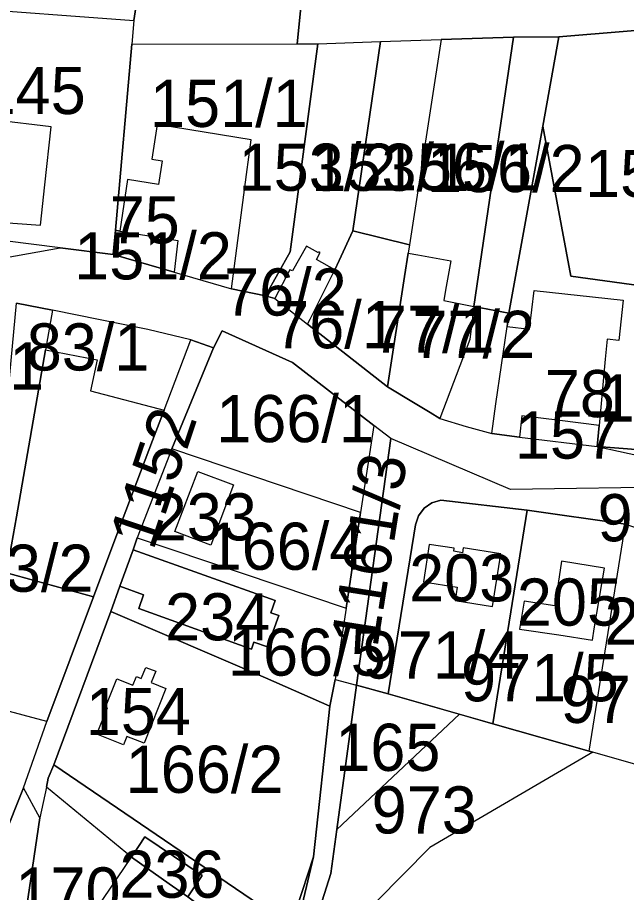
# Model space of a CAD drawing. Extents: x -623250 to -619626, y -1079612 to -1075424.
# Drawn here: x -621418.9 to -621289.7, y -1077664.2 to -1077478.6 of the extents above; entities that cross this region are included whole.
import ezdxf

# ---------------------------------------------------------------- set-up
doc = ezdxf.new("R2010")
doc.units = 0
for name, color, linetype in [('Hranice převzatá (k_ú_Džbánov - vnitřní obvod)', 7, 'Continuous'), ('Hranice šetřená (k_ú_Džbánov - vnitřní obvod)', 7, 'Continuous'), ('Parcela nároku', 7, 'Continuous'), ('Parcelní číslo', 7, 'Continuous')]:
    doc.layers.add(name, color=color, linetype=linetype)

msp = doc.modelspace()

# ---------------------------------------------------------------- linework, layer by layer
at = {"layer": 'Hranice převzatá (k_ú_Džbánov - vnitřní obvod)'}
msp.add_lwpolyline([(-621214.74, -1077657.83), (-621238.69, -1077651.01), (-621258.47, -1077645.38), (-621278, -1077639.82), (-621297.64, -1077634.23), (-621318.07, -1077628.41), (-621340.28, -1077622.09)], dxfattribs=at)
at = {"layer": 'Hranice šetřená (k_ú_Džbánov - vnitřní obvod)'}
msp.add_lwpolyline([(-621340.28, -1077622.09), (-621346.96, -1077620.27), (-621351.15, -1077650.83), (-621352.43, -1077660.2), (-621359.74, -1077683.39), (-621370.61, -1077717.85), (-621377.7, -1077716.06), (-621379.95, -1077714.81)], dxfattribs=at)
at = {"layer": 'Parcela nároku'}
for points in [[(-621431.19, -1077464.42), (-621432.42, -1077476.42), (-621394.2, -1077479.27), (-621389.22, -1077446.41), (-621387.12, -1077432.52), (-621431.55, -1077429.78), (-621432.54, -1077450.72)], [(-621355.58, -1077444.76), (-621359.53, -1077484.2), (-621355.15, -1077484.19), (-621341.9, -1077483.74), (-621329.01, -1077483.3), (-621313.65, -1077482.77), (-621304.05, -1077482.73), (-621260.58, -1077479.13), (-621259.56, -1077479.1), (-621135.81, -1077472.04), (-621135.22, -1077433.98), (-621245.55, -1077439.34)], [(-621355.58, -1077444.76), (-621389.22, -1077446.41), (-621394.2, -1077479.27), (-621394.64, -1077484.28), (-621359.53, -1077484.2)], [(-621432.87, -1077520.7), (-621423.85, -1077521.6), (-621423.86, -1077521.97), (-621413.99, -1077522.64), (-621413.07, -1077514.1), (-621411.75, -1077501.83), (-621423.64, -1077500.41), (-621431.06, -1077499.52), (-621431.34, -1077502.84), (-621433.01, -1077498.77), (-621432.42, -1077476.42), (-621394.2, -1077479.27), (-621394.64, -1077484.28), (-621398.13, -1077523.76), (-621398.59, -1077528.92), (-621409.83, -1077527.49), (-621432.82, -1077524.57), (-621434.85, -1077520.63), (-621435.53, -1077511.12), (-621432.08, -1077511.42)], [(-621304.05, -1077482.73), (-621307.47, -1077501.65), (-621301.53, -1077533.51), (-621281.39, -1077536.25), (-621283.3, -1077546.96), (-621271.81, -1077549.22), (-621270.79, -1077541.41), (-621270.05, -1077537.9), (-621260.58, -1077479.13)], [(-621347.75, -1077523.85), (-621341.9, -1077483.74), (-621329.01, -1077483.3), (-621335.75, -1077526.83)], [(-621329.01, -1077483.3), (-621335.75, -1077526.83), (-621336.02, -1077528.59), (-621333.93, -1077528.97), (-621326.98, -1077530.23), (-621328.07, -1077536.44), (-621328.45, -1077538.64), (-621322.05, -1077539.89), (-621313.65, -1077482.77)], [(-621313.65, -1077482.77), (-621322.05, -1077539.89), (-621314.63, -1077541.33), (-621307.47, -1077501.65), (-621304.05, -1077482.73)], [(-621359.53, -1077484.2), (-621355.15, -1077484.19), (-621361.03, -1077528.31), (-621366.28, -1077537.63), (-621373.52, -1077536.18), (-621370.3, -1077511.94), (-621369.32, -1077504.6), (-621389.25, -1077501.32), (-621390.36, -1077508.65), (-621388.23, -1077509), (-621389, -1077514.06), (-621395.53, -1077513.01), (-621397.17, -1077523.92), (-621398.13, -1077523.76), (-621394.64, -1077484.28)], [(-621355.48, -1077529.95), (-621354.67, -1077528.47), (-621354.93, -1077528.31), (-621355.07, -1077528.56), (-621357.57, -1077527.16), (-621360.55, -1077532.38), (-621361.1, -1077532.12), (-621364.27, -1077538.26), (-621366.28, -1077537.63), (-621361.03, -1077528.31), (-621355.15, -1077484.19), (-621341.9, -1077483.74), (-621347.75, -1077523.85), (-621350.66, -1077530.14), (-621351.57, -1077532.11)], [(-621432.08, -1077511.42), (-621432.87, -1077520.7), (-621423.85, -1077521.6), (-621423.86, -1077521.97), (-621413.99, -1077522.64), (-621413.07, -1077514.1), (-621411.75, -1077501.83), (-621423.64, -1077500.41), (-621431.06, -1077499.52), (-621431.34, -1077502.84)], [(-621395.53, -1077513.01), (-621397.17, -1077523.92), (-621384.86, -1077525.91), (-621385.68, -1077532.66), (-621373.52, -1077536.18), (-621370.3, -1077511.94), (-621369.32, -1077504.6), (-621389.25, -1077501.32), (-621390.36, -1077508.65), (-621388.23, -1077509), (-621389, -1077514.06)], [(-621291.33, -1077547.16), (-621293.81, -1077546.85), (-621294.21, -1077551.1), (-621295.52, -1077565.19), (-621295.93, -1077569.59), (-621282.23, -1077570.67), (-621274.84, -1077571.34), (-621272.51, -1077554.6), (-621271.81, -1077549.22), (-621283.3, -1077546.96), (-621281.39, -1077536.25), (-621301.53, -1077533.51), (-621307.47, -1077501.65), (-621314.63, -1077541.33), (-621315.03, -1077544.15), (-621310.24, -1077544.76), (-621309.31, -1077536.52), (-621290.37, -1077538.6)], [(-621398.13, -1077523.76), (-621397.17, -1077523.92), (-621384.86, -1077525.91), (-621385.68, -1077532.66), (-621398.59, -1077528.92)], [(-621350.66, -1077530.14), (-621347.75, -1077523.85), (-621335.75, -1077526.83), (-621336.02, -1077528.59), (-621336.78, -1077533.53), (-621340.4, -1077556.93), (-621357.38, -1077543.67), (-621356.83, -1077542.6), (-621354.05, -1077537.06), (-621351.57, -1077532.11)], [(-621351.57, -1077532.11), (-621355.48, -1077529.95), (-621354.67, -1077528.47), (-621354.93, -1077528.31), (-621355.07, -1077528.56), (-621357.57, -1077527.16), (-621360.55, -1077532.38), (-621361.1, -1077532.12), (-621364.27, -1077538.26), (-621357.38, -1077543.67), (-621356.83, -1077542.6), (-621354.05, -1077537.06)], [(-621333.93, -1077528.97), (-621326.98, -1077530.23), (-621328.07, -1077536.44), (-621328.45, -1077538.64), (-621322.05, -1077539.89), (-621322.95, -1077546.93), (-621329.3, -1077563.67), (-621331.35, -1077562.43), (-621334.85, -1077560.3), (-621340.4, -1077556.93), (-621336.78, -1077533.53), (-621336.02, -1077528.59)], [(-621309.31, -1077536.52), (-621290.37, -1077538.6), (-621291.33, -1077547.16), (-621293.81, -1077546.85), (-621294.21, -1077551.1), (-621295.52, -1077565.19), (-621303.81, -1077564.12), (-621311.89, -1077563.08), (-621312.4, -1077567.64), (-621318.29, -1077566.85), (-621317.39, -1077560.56), (-621315.03, -1077544.15), (-621310.24, -1077544.76)], [(-621421.37, -1077563.54), (-621419.1, -1077539.22), (-621411.47, -1077540.68), (-621412.94, -1077549.12), (-621419.12, -1077584.51), (-621421.21, -1077596.44), (-621402.8, -1077601.53), (-621412.65, -1077627.97), (-621456.87, -1077616.12), (-621445.88, -1077587.23), (-621441.98, -1077574.44), (-621439.96, -1077561.89)], [(-621402, -1077551.23), (-621403.4, -1077557.8), (-621387.79, -1077561.88), (-621382.14, -1077546.96), (-621391.27, -1077544.81), (-621411.47, -1077540.68), (-621412.94, -1077549.12)], [(-621322.95, -1077546.93), (-621329.3, -1077563.67), (-621323.69, -1077565.39), (-621318.29, -1077566.85), (-621317.39, -1077560.56), (-621315.03, -1077544.15), (-621314.63, -1077541.33), (-621322.05, -1077539.89)], [(-621377.29, -1077548.7), (-621375.5, -1077545.11), (-621360.55, -1077551.81), (-621343.27, -1077565.17), (-621346.09, -1077583.64), (-621386.18, -1077570.1)], [(-621390.24, -1077568.33), (-621387.79, -1077561.88), (-621382.14, -1077546.96), (-621377.29, -1077548.7), (-621386.18, -1077570.1), (-621393.48, -1077588.98), (-621394.38, -1077591.5), (-621397.15, -1077599.25), (-621399.07, -1077604.61), (-621411.21, -1077637.14), (-621412.36, -1077639.98), (-621412.76, -1077641.87), (-621414.14, -1077648.39), (-621417.6, -1077642.03), (-621412.65, -1077627.97), (-621402.8, -1077601.53), (-621398.43, -1077589.98)], [(-621419.12, -1077584.51), (-621412.94, -1077549.12), (-621402, -1077551.23), (-621403.4, -1077557.8), (-621387.79, -1077561.88), (-621390.24, -1077568.33), (-621398.43, -1077589.98), (-621402.8, -1077601.53), (-621421.21, -1077596.44)], [(-621311.89, -1077563.08), (-621312.4, -1077567.64), (-621295.93, -1077569.59), (-621295.52, -1077565.19), (-621303.81, -1077564.12)], [(-621343.27, -1077565.17), (-621346.09, -1077583.64), (-621349.19, -1077603.93), (-621351.52, -1077619.03), (-621346.96, -1077620.27), (-621339.68, -1077567.94)], [(-621339.68, -1077567.94), (-621346.96, -1077620.27), (-621340.28, -1077622.09), (-621334.49, -1077586.23), (-621333.8, -1077584.35), (-621332.65, -1077582.72), (-621331.01, -1077581.57), (-621329.11, -1077580.97), (-621310.78, -1077583.14), (-621289.92, -1077586.08), (-621270.57, -1077592.5), (-621251.47, -1077598.84), (-621232.16, -1077609.38), (-621231.6, -1077605.46), (-621230.97, -1077601.51), (-621230.3, -1077597.33), (-621249.89, -1077587.61), (-621276.92, -1077578.18), (-621314.29, -1077578.72)], [(-621346.09, -1077583.64), (-621386.18, -1077570.1), (-621393.48, -1077588.98), (-621349.19, -1077603.93)], [(-621282.23, -1077570.67), (-621295.93, -1077569.59), (-621263.21, -1077576.78), (-621199.09, -1077596.49), (-621153.39, -1077607.74), (-621200.71, -1077591.9), (-621232.07, -1077582.6), (-621241.7, -1077580.71), (-621254.93, -1077577.63), (-621254.52, -1077575.41), (-621263.69, -1077572.48), (-621263.56, -1077571.13), (-621274.84, -1077571.34)], [(-621377.87, -1077590.51), (-621385.48, -1077587.63), (-621380.65, -1077574.9), (-621373.05, -1077577.75)], [(-621385.48, -1077587.63), (-621380.65, -1077574.9), (-621373.05, -1077577.75), (-621377.87, -1077590.51)], [(-621329.11, -1077580.97), (-621331.01, -1077581.57), (-621332.65, -1077582.72), (-621333.8, -1077584.35), (-621334.49, -1077586.23), (-621340.28, -1077622.09), (-621325.15, -1077626.4), (-621318.07, -1077628.41), (-621310.78, -1077583.14)], [(-621289.92, -1077586.08), (-621310.78, -1077583.14), (-621318.07, -1077628.41), (-621297.64, -1077634.23)], [(-621297.64, -1077634.23), (-621289.92, -1077586.08), (-621270.57, -1077592.5), (-621278, -1077639.82), (-621296.82, -1077634.46)], [(-621397.15, -1077599.25), (-621392.15, -1077601.05), (-621393.18, -1077603.97), (-621369.26, -1077612.57), (-621368.73, -1077611.12), (-621365.86, -1077612.14), (-621363.47, -1077605.49), (-621365.14, -1077604.87), (-621364.2, -1077602.27), (-621394.38, -1077591.5), (-621393.48, -1077588.98), (-621349.19, -1077603.93), (-621351.52, -1077619.03), (-621352.61, -1077624.67), (-621366.26, -1077618.67), (-621399.07, -1077604.61)], [(-621318.11, -1077603.53), (-621316.37, -1077592.4), (-621324.33, -1077591.13), (-621324.48, -1077592.15), (-621326.35, -1077591.84), (-621326.26, -1077591.2), (-621331.53, -1077590.38), (-621332.78, -1077598.34), (-621325.65, -1077599.48), (-621326.07, -1077602.28)], [(-621324.33, -1077591.13), (-621324.48, -1077592.15), (-621326.35, -1077591.84), (-621326.26, -1077591.2), (-621331.53, -1077590.38), (-621332.78, -1077598.34), (-621325.65, -1077599.48), (-621326.07, -1077602.28), (-621318.11, -1077603.53), (-621316.37, -1077592.4)], [(-621365.14, -1077604.87), (-621363.47, -1077605.49), (-621365.86, -1077612.14), (-621368.73, -1077611.12), (-621369.26, -1077612.57), (-621393.18, -1077603.97), (-621392.15, -1077601.05), (-621397.15, -1077599.25), (-621394.38, -1077591.5), (-621364.2, -1077602.27)], [(-621296.53, -1077608.32), (-621294.38, -1077595.42), (-621303.47, -1077593.91), (-621304.91, -1077603.39), (-621311.37, -1077602.4), (-621312.36, -1077608.35), (-621304.05, -1077609.56), (-621296.91, -1077610.71)], [(-621304.91, -1077603.39), (-621311.37, -1077602.4), (-621312.36, -1077608.35), (-621304.05, -1077609.56), (-621296.91, -1077610.71), (-621296.53, -1077608.32), (-621294.38, -1077595.42), (-621303.47, -1077593.91)], [(-621399.07, -1077604.61), (-621366.26, -1077618.67), (-621352.61, -1077624.67), (-621356.07, -1077656.62), (-621360.94, -1077671.33), (-621411.21, -1077637.14)], [(-621412.65, -1077627.97), (-621456.87, -1077616.12), (-621468.32, -1077652.78), (-621426.47, -1077663.99), (-621417.6, -1077642.03)], [(-621394.43, -1077620.26), (-621393.64, -1077618.43), (-621392.66, -1077618.85), (-621391.66, -1077616.46), (-621389.58, -1077617.29), (-621390.53, -1077619.67), (-621387.39, -1077620.93), (-621392.05, -1077632.56), (-621395.68, -1077631.11), (-621396.4, -1077632.92), (-621402.08, -1077630.65), (-621401.35, -1077628.84), (-621399.82, -1077625.03), (-621400.19, -1077624.88), (-621397.79, -1077618.9)], [(-621387.39, -1077620.93), (-621392.05, -1077632.56), (-621395.68, -1077631.11), (-621396.4, -1077632.92), (-621402.08, -1077630.65), (-621401.35, -1077628.84), (-621399.82, -1077625.03), (-621400.19, -1077624.88), (-621397.79, -1077618.9), (-621394.43, -1077620.26), (-621393.64, -1077618.43), (-621392.66, -1077618.85), (-621391.66, -1077616.46), (-621389.58, -1077617.29), (-621390.53, -1077619.67)], [(-621351.15, -1077650.83), (-621346.96, -1077620.27), (-621340.28, -1077622.09), (-621325.15, -1077626.4)], [(-621325.15, -1077626.4), (-621318.07, -1077628.41), (-621297.64, -1077634.23), (-621296.82, -1077634.46), (-621331.45, -1077654.68), (-621359.74, -1077683.39), (-621352.43, -1077660.2), (-621351.15, -1077650.83)], [(-621412.36, -1077639.98), (-621411.21, -1077637.14), (-621360.94, -1077671.33), (-621364.39, -1077678.9), (-621365.89, -1077677.89), (-621374.5, -1077671.38), (-621382.78, -1077665.12), (-621379.74, -1077660.62), (-621391.87, -1077652.44), (-621394.73, -1077656.69), (-621412.76, -1077641.87)], [(-621468.32, -1077652.78), (-621469.02, -1077655.02), (-621472.37, -1077671.75), (-621379.95, -1077714.81), (-621377.39, -1077695.22), (-621386.69, -1077709.23), (-621408.45, -1077694.77), (-621405.71, -1077690.62), (-621402.58, -1077685.89), (-621410.62, -1077680.48), (-621418.22, -1077675.64), (-621414.14, -1077648.39), (-621417.6, -1077642.03), (-621426.47, -1077663.99)], [(-621414.14, -1077648.39), (-621418.22, -1077675.64), (-621410.62, -1077680.48), (-621406.69, -1077674.58), (-621408.69, -1077673.25), (-621405.55, -1077668.55), (-621403.62, -1077669.9), (-621394.73, -1077656.69), (-621412.76, -1077641.87)], [(-621391.87, -1077652.44), (-621379.74, -1077660.62), (-621382.78, -1077665.12), (-621386.75, -1077662.39), (-621394.73, -1077656.69)], [(-621364.39, -1077678.9), (-621360.94, -1077671.33), (-621356.07, -1077656.62), (-621361.81, -1077680.91), (-621375.21, -1077712.24), (-621395.2, -1077773.48), (-621413.63, -1077833.01), (-621448.87, -1077932.09), (-621484.15, -1078031.22), (-621531.47, -1078143.68), (-621559.31, -1078200.97), (-621633.61, -1078348.03), (-621651.3, -1078390.37), (-621666.67, -1078429.48), (-621674.85, -1078456.45), (-621678.32, -1078456.03), (-621652.48, -1078389.36), (-621636.77, -1078350.51), (-621560.48, -1078200.14), (-621532.5, -1078143.13), (-621485.18, -1078030.89), (-621450, -1077931.7), (-621414.98, -1077832.91), (-621377.7, -1077716.06)], [(-621374.5, -1077671.38), (-621365.89, -1077677.89), (-621377.39, -1077695.22), (-621386.69, -1077709.23), (-621408.45, -1077694.77), (-621405.71, -1077690.62), (-621402.58, -1077685.89), (-621410.62, -1077680.48), (-621406.69, -1077674.58), (-621408.69, -1077673.25), (-621405.55, -1077668.55), (-621403.62, -1077669.9), (-621394.73, -1077656.69), (-621386.75, -1077662.39), (-621382.78, -1077665.12)]]:
    msp.add_lwpolyline(points, close=True, dxfattribs=at)
for points in [[(-621440.35, -1077532.9), (-621409.83, -1077527.49), (-621432.82, -1077524.57)], [(-621440.35, -1077532.9), (-621409.83, -1077527.49), (-621398.59, -1077528.92), (-621385.68, -1077532.66), (-621373.52, -1077536.18), (-621366.28, -1077537.63), (-621364.27, -1077538.26), (-621357.38, -1077543.67), (-621340.4, -1077556.93), (-621334.85, -1077560.3), (-621331.35, -1077562.43), (-621329.3, -1077563.67), (-621323.69, -1077565.39), (-621318.29, -1077566.85), (-621312.4, -1077567.64), (-621295.93, -1077569.59), (-621263.21, -1077576.78), (-621199.09, -1077596.49)], [(-621168.66, -1077615.74), (-621206.08, -1077609.32), (-621211.44, -1077608.6), (-621225.28, -1077599.82), (-621230.3, -1077597.33), (-621249.89, -1077587.61), (-621276.92, -1077578.18), (-621314.29, -1077578.72), (-621339.68, -1077567.94), (-621343.27, -1077565.17), (-621360.55, -1077551.81), (-621375.5, -1077545.11), (-621377.29, -1077548.7), (-621382.14, -1077546.96), (-621391.27, -1077544.81), (-621411.47, -1077540.68), (-621419.1, -1077539.22)], [(-621595.12, -1078274.48), (-621557.95, -1078201.7), (-621530.38, -1078144.73), (-621482.76, -1078032.4), (-621447.54, -1077932.95), (-621412.5, -1077833.54), (-621393.67, -1077773.75), (-621374.06, -1077714.41), (-621361.81, -1077680.91), (-621356.07, -1077656.62), (-621352.61, -1077624.67), (-621351.52, -1077619.03), (-621346.96, -1077620.27), (-621351.15, -1077650.83), (-621352.43, -1077660.2), (-621359.74, -1077683.39), (-621370.61, -1077717.85), (-621410.49, -1077834.12), (-621445.17, -1077933.59), (-621480.01, -1078033.01), (-621527.76, -1078145.86), (-621554.92, -1078203.35), (-621592.05, -1078275.81)], [(-621413.47, -1078234.45), (-621340.92, -1078060.83), (-621287.56, -1077905.65), (-621260.76, -1077824.45), (-621208.08, -1077659.7), (-621214.74, -1077657.83), (-621238.69, -1077651.01), (-621258.47, -1077645.38), (-621278, -1077639.82), (-621296.82, -1077634.46), (-621331.45, -1077654.68), (-621359.74, -1077683.39), (-621370.61, -1077717.85), (-621410.49, -1077834.12), (-621445.17, -1077933.59), (-621480.01, -1078033.01), (-621527.76, -1078145.86), (-621554.92, -1078203.35), (-621592.05, -1078275.81)]]:
    msp.add_lwpolyline(points, dxfattribs=at)

# ---------------------------------------------------------------- texts
at = {"layer": 'Parcelní číslo'}
for s, p in [('145', (-621426.73, -1077499.1)), ('151/1', (-621390.78, -1077501.84)), ('153/2', (-621371.99, -1077515.38)), ('153/1', (-621356.55, -1077515.39)), ('156/1', (-621341.59, -1077515.29)), ('156/2', (-621332.04, -1077515.66)), ('159', (-621298.48, -1077516.71)), ('75', (-621399.35, -1077526.55)), ('151/2', (-621406.87, -1077534.17)), ('76/2', (-621375.07, -1077541.85)), ('76/1', (-621364.44, -1077548.78)), ('77/1', (-621343.71, -1077549.73)), ('77/2', (-621335.12, -1077550.83)), ('83/1', (-621416.94, -1077553.5)), ('169/1', (-621446.7, -1077557.53)), ('78', (-621307.03, -1077563.4)), ('158', (-621295.4, -1077564.32)), ('166/1', (-621376.73, -1077568.7)), ('157', (-621313.37, -1077572.19)), ('233', (-621390.43, -1077589.53)), ('971/3', (-621295.83, -1077589.72)), ('166/4', (-621378.78, -1077595.77)), ('83/2', (-621428.81, -1077600.43)), ('203', (-621335.81, -1077602.48)), ('205', (-621312.95, -1077607.61)), ('234', (-621387.59, -1077610.73)), ('204', (-621294.36, -1077611.67)), ('166/5', (-621374.24, -1077618.22)), ('971/4', (-621345.68, -1077618.84)), ('971/5', (-621324.8, -1077623.66)), ('971/6', (-621303.66, -1077628.25)), ('154', (-621404.41, -1077630.81)), ('165', (-621351.48, -1077638.42)), ('166/2', (-621395.94, -1077643.08)), ('973', (-621343.77, -1077651.7)), ('236', (-621397.28, -1077665.32)), ('170', (-621419.35, -1077668.89))]:
    msp.add_text(s, height=10, dxfattribs=at).set_placement(p)
for s, rotation, p in [('1152', 71.5204, (-621390.11, -1077591.88)), ('1161/3', 81.0274, (-621342.55, -1077612.47))]:
    msp.add_text(s, height=10, rotation=rotation, dxfattribs=at).set_placement(p)

doc.saveas('drawing.dxf')
